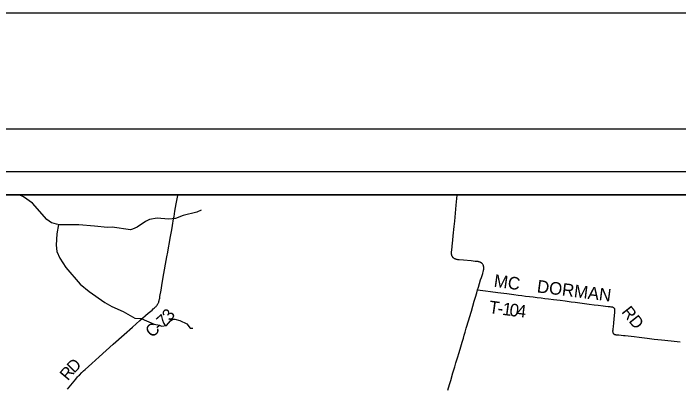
# Model space of a CAD drawing. Extents: x -13.9 to 69.1, y -25.2 to 26.1.
# Drawn here: x 5.08 to 7.963, y 20.383 to 22 of the extents above; entities that cross this region are included whole.
import ezdxf

# ---------------------------------------------------------------- set-up
doc = ezdxf.new("R2010")
doc.units = 0
for name, color, linetype in [('GM_X_County_Road', 7, 'Continuous'), ('GM_X_County_Road_Text', 7, 'Continuous'), ('GM_X_Minor_River', 7, 'Continuous'), ('GM_X_Township', 7, 'Continuous'), ('GM_X_Township_Road', 7, 'Continuous'), ('GM_X_Township_Road_Text', 7, 'Continuous'), ('SH_Border', 7, 'Continuous'), ('SH_Cut_Line', 7, 'Continuous'), ('SH_Data', 7, 'Continuous')]:
    doc.layers.add(name, color=color, linetype=linetype)

msp = doc.modelspace()

# ---------------------------------------------------------------- linework, layer by layer
at = {"layer": 'GM_X_County_Road'}
msp.add_lwpolyline([(5.314, 20.3724), (5.3499, 20.416), (5.3582, 20.4256), (5.3621, 20.4298), (5.3657, 20.4336), (5.3767, 20.4445), (5.3842, 20.4515), (5.391, 20.4577), (5.4197, 20.4838), (5.4511, 20.512), (5.4825, 20.5402), (5.5127, 20.5672), (5.5599, 20.6094), (5.5963, 20.6414), (5.6283, 20.6696), (5.6643, 20.7012), (5.6807, 20.7154), (5.6858, 20.7199), (5.6905, 20.7241), (5.6959, 20.7291), (5.698, 20.7313), (5.7006, 20.7341), (5.7023, 20.7362), (5.7036, 20.738), (5.7049, 20.7399), (5.7064, 20.7425), (5.7076, 20.7449), (5.7086, 20.747), (5.7096, 20.7499), (5.7106, 20.7527), (5.7115, 20.756), (5.7123, 20.7592), (5.713, 20.7622), (5.7138, 20.7662), (5.7151, 20.7733), (5.7199, 20.8014), (5.725, 20.8318), (5.7323, 20.8739), (5.735, 20.8891), (5.7394, 20.9136), (5.7451, 20.9458), (5.7487, 20.9662), (5.752, 20.9849), (5.756, 21.0077), (5.7592, 21.0258), (5.766, 21.0632), (5.7692, 21.0812), (5.7743, 21.1098), (5.7763, 21.1209), (5.7802, 21.1439), (5.7857, 21.1753), (5.7921, 21.2114), (5.7926, 21.2145)], dxfattribs=at)
at = {"layer": 'GM_X_Minor_River'}
for points in [[(5.8929, 21.1472), (5.8755, 21.1391), (5.8149, 21.1244), (5.7827, 21.1115), (5.7527, 21.1089), (5.7028, 21.1138), (5.6704, 21.1076), (5.6524, 21.0988), (5.6162, 21.0734), (5.5962, 21.0658), (5.587, 21.0631), (5.5073, 21.0741), (5.4877, 21.0727), (5.4312, 21.0785), (5.3642, 21.0846), (5.2792, 21.0841), (5.2672, 21.0868), (5.2561, 21.0903), (5.2457, 21.0927), (5.225, 21.108), (5.1625, 21.1787), (5.1241, 21.2049), (5.1054, 21.2145)], [(5.2752, 21.085), (5.2678, 21.045), (5.2647, 20.9967), (5.2689, 20.9683), (5.2806, 20.9393), (5.3072, 20.8995), (5.3694, 20.8267), (5.409, 20.7953), (5.4756, 20.7475), (5.506, 20.7309), (5.5559, 20.7092), (5.6057, 20.6802), (5.6336, 20.6789), (5.6895, 20.6545), (5.7124, 20.6504), (5.7224, 20.6462), (5.7427, 20.648), (5.7602, 20.6684), (5.7715, 20.6754), (5.7802, 20.676), (5.8007, 20.6698), (5.8308, 20.6557), (5.846, 20.6365), (5.8568, 20.6363)]]:
    msp.add_lwpolyline(points, dxfattribs=at)
at = {"layer": 'GM_X_Township'}
msp.add_lwpolyline([(8.0976, 21.2145), (2.668, 21.2145), (2.5713, 21.1249), (2.5376, 21.0933), (2.5207, 21.0774), (2.9282, 20.5283), (2.3149, 19.9943), (2.3345, 19.9924), (2.4186, 19.989), (2.4692, 19.987), (2.5176, 19.987), (2.5995, 20.0118), (2.5714, 18.9023), (4.5288, 18.7816), (7.8661, 18.459), (7.9988, 20.0382), (8.0428, 20.5625)], close=True, dxfattribs=at)
at = {"layer": 'GM_X_Township_Road'}
for points in [[(7.0916, 20.8032), (7.0949, 20.8144), (7.1044, 20.8455), (7.1079, 20.8568), (7.1135, 20.8742), (7.116, 20.8822), (7.1167, 20.8847), (7.1172, 20.8867), (7.1176, 20.889), (7.1179, 20.8905), (7.1181, 20.892), (7.1183, 20.8944), (7.1184, 20.8957), (7.1183, 20.8975), (7.1182, 20.8991), (7.1181, 20.9005), (7.1179, 20.9017), (7.1176, 20.9032), (7.1173, 20.9048), (7.1169, 20.9061), (7.1162, 20.908), (7.1157, 20.9094), (7.115, 20.9108), (7.1143, 20.912), (7.1137, 20.913), (7.1123, 20.9148), (7.1112, 20.9161), (7.1103, 20.9169), (7.1094, 20.9178), (7.1085, 20.9185), (7.1076, 20.9191), (7.1067, 20.9198), (7.1052, 20.9207), (7.104, 20.9214), (7.1027, 20.922), (7.1015, 20.9226), (7.1003, 20.923), (7.0988, 20.9236), (7.0972, 20.9241), (7.0959, 20.9244), (7.0939, 20.9248), (7.0913, 20.9251), (7.0812, 20.9261), (7.0636, 20.9278), (7.03, 20.9309), (7.0108, 20.9328), (7.0076, 20.9332), (7.0057, 20.9334), (7.0035, 20.9337), (7.0009, 20.9342), (6.9992, 20.9346), (6.9976, 20.935), (6.9954, 20.9357), (6.9935, 20.9365), (6.9917, 20.9374), (6.9905, 20.9381), (6.9892, 20.9388), (6.9881, 20.9396), (6.9867, 20.9408), (6.9856, 20.9419), (6.9845, 20.943), (6.9837, 20.944), (6.9828, 20.9452), (6.982, 20.9464), (6.9812, 20.9481), (6.9805, 20.9495), (6.9801, 20.9507), (6.9797, 20.9518), (6.9794, 20.953), (6.9791, 20.9545), (6.9789, 20.9558), (6.9786, 20.9577), (6.9785, 20.9593), (6.9784, 20.9613), (6.9784, 20.963), (6.9785, 20.9653), (6.9786, 20.9685), (6.9788, 20.9705), (6.979, 20.9724), (6.981, 20.9914), (6.9838, 21.0174), (6.9858, 21.0369), (6.9902, 21.0776), (6.9924, 21.1001), (6.9957, 21.135), (6.9986, 21.1693), (7.0023, 21.2126), (7.0025, 21.2145)], [(6.9627, 20.3691), (6.9695, 20.3924), (6.9748, 20.4105), (6.9845, 20.4428), (6.9923, 20.4689), (6.9975, 20.4865), (7.004, 20.5081), (7.0111, 20.5319), (7.0185, 20.5563), (7.0242, 20.5755), (7.0299, 20.5941), (7.0336, 20.6064), (7.0373, 20.6195), (7.0423, 20.6364), (7.053, 20.6726), (7.0562, 20.6834), (7.0643, 20.7106), (7.077, 20.7536), (7.0822, 20.7712), (7.0875, 20.7893), (7.0916, 20.8032)], [(7.0916, 20.8032), (7.1134, 20.8003), (7.1262, 20.7987), (7.1474, 20.7958), (7.1786, 20.7916), (7.1924, 20.7898), (7.2176, 20.7864), (7.2482, 20.7823), (7.267, 20.7799), (7.2834, 20.7781), (7.2994, 20.7761), (7.3164, 20.7739), (7.3317, 20.772), (7.35, 20.7697), (7.3668, 20.7677), (7.3831, 20.7654), (7.3986, 20.7635), (7.4195, 20.761), (7.4343, 20.7592), (7.4491, 20.7574), (7.4711, 20.7546), (7.4969, 20.7514), (7.5134, 20.7493), (7.5337, 20.7466), (7.5545, 20.7439), (7.5748, 20.7414), (7.5968, 20.7385), (7.6143, 20.7361), (7.6353, 20.7334), (7.6462, 20.7321), (7.6575, 20.7307), (7.6637, 20.7302), (7.6688, 20.7298), (7.6699, 20.7296), (7.6712, 20.7294), (7.6732, 20.7291), (7.6743, 20.7288), (7.6753, 20.7285), (7.6766, 20.7281), (7.6776, 20.7277), (7.6783, 20.7272), (7.6791, 20.7268), (7.6798, 20.7263), (7.6806, 20.7257), (7.6811, 20.7252), (7.6818, 20.7245), (7.6825, 20.7236), (7.6829, 20.7229), (7.6834, 20.7221), (7.6838, 20.7213), (7.6841, 20.7205), (7.6843, 20.7196), (7.6845, 20.7186), (7.6848, 20.7175), (7.685, 20.7163), (7.6851, 20.7152), (7.6851, 20.7139), (7.6852, 20.7127), (7.6851, 20.7113), (7.6851, 20.7098), (7.6848, 20.7068), (7.6831, 20.6908), (7.6817, 20.6772), (7.6798, 20.6583), (7.6784, 20.6447), (7.6772, 20.6325), (7.6766, 20.6269), (7.6765, 20.6246), (7.6765, 20.6233), (7.6767, 20.621), (7.6768, 20.6201), (7.677, 20.6192), (7.6771, 20.6185), (7.6773, 20.6177), (7.6776, 20.6169), (7.678, 20.6161), (7.6783, 20.6154), (7.6789, 20.6145), (7.6794, 20.6137), (7.6799, 20.6132), (7.6805, 20.6127), (7.6813, 20.6119), (7.6829, 20.6109), (7.6836, 20.6105), (7.6843, 20.6101), (7.6849, 20.6098), (7.6857, 20.6096), (7.6867, 20.6093), (7.6875, 20.6091), (7.6884, 20.6089), (7.6907, 20.6085), (7.6928, 20.6083), (7.7033, 20.6075), (7.7237, 20.6054), (7.7303, 20.6048), (7.7699, 20.6001), (7.7913, 20.5976), (7.8265, 20.5935), (7.8567, 20.5898), (7.888, 20.5862), (7.9298, 20.5816), (7.9686, 20.577)]]:
    msp.add_lwpolyline(points, dxfattribs=at)
at = {"layer": 'SH_Border'}
msp.add_lwpolyline([(1.5, 21.5), (33.5, 21.5), (33.5, 0.5), (1.5, 0.5)], close=True, dxfattribs=at)
at = {"layer": 'SH_Cut_Line'}
msp.add_lwpolyline([(0, 0), (34, 0), (34, 22), (0, 22)], close=True, dxfattribs=at)
at = {"layer": 'SH_Data'}
for p, q in [((1.6571, 21.3145), (8.6571, 21.3145)), ((1.7571, 21.2145), (8.5571, 21.2145))]:
    msp.add_line(p, q, dxfattribs=at)

# ---------------------------------------------------------------- texts
at = {"layer": 'GM_X_County_Road_Text'}
for s, height, rotation, p in [('3', 0.0521, 52.6145, (5.7602, 20.6649)), ('7', 0.0529, 41.485, (5.7285, 20.6355)), ('C', 0.0529, 41.2245, (5.6801, 20.593)), ('-', 0.0529, 41.2541, (5.7123, 20.6213)), ('D', 0.0526, 45.0745, (5.3429, 20.4389)), ('R', 0.0523, 50.0788, (5.316, 20.4066))]:
    msp.add_text(s, height=height, rotation=rotation, dxfattribs=at).set_placement(p)
at = {"layer": 'GM_X_Township_Road_Text'}
for s, height, rotation, p in [('MC', 0.05432, 352.0544, (7.1595, 20.8168)), ('DORMAN', 0.05433, 352.7752, (7.3464, 20.7922)), ('T', 0.0543, 352.2165, (7.1379, 20.7028)), ('1', 0.0543, 352.2676, (7.1961, 20.6949)), ('0', 0.0543, 352.4366, (7.2271, 20.6907)), ('4', 0.0543, 353.1802, (7.2587, 20.6865)), ('RD', 0.05218, 308.3839, (7.7127, 20.7066)), ('-', 0.0543, 352.225, (7.1755, 20.6977))]:
    msp.add_text(s, height=height, rotation=rotation, dxfattribs=at).set_placement(p)

doc.saveas('drawing.dxf')
